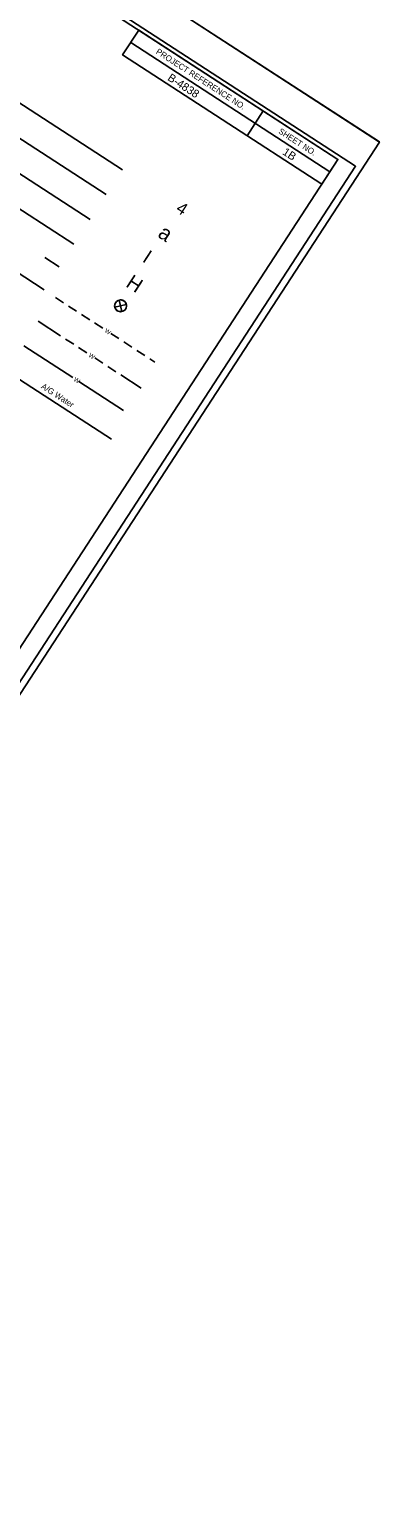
# Model space of a CAD drawing. Extents: x 2291197 to 2302790, y 592892 to 604246.
# Drawn here: x 2298300 to 2299243, y 592892 to 596884 of the extents above; entities that cross this region are included whole.
import ezdxf

# ---------------------------------------------------------------- set-up
doc = ezdxf.new("R2010")
doc.units = 0
for name, color, linetype in [('Default', 7, 'Continuous'), ('Prop Shade Light', 7, 'Continuous'), ('Sheet Cutting Line CELL', 7, 'Continuous'), ('Sheet Data Field CELL', 7, 'Continuous'), ('Sheet Plot Border Inside CELL', 7, 'Continuous'), ('Sheet Plot Border Outside CELL', 7, 'Continuous'), ('Sheet Symbology CELL', 7, 'Continuous')]:
    doc.layers.add(name, color=color, linetype=linetype)

# ---------------------------------------------------------------- blocks, each defined once
blk = doc.blocks.new('EXIST UTILITIES WATER TEST HOLE SUE LOS A')
at = {"layer": 'Default'}
for points in [[(0.043, 0.043), (-0.043, -0.043), (0, 0), (-0.043, 0.043), (0.043, -0.043)], [(-0.043, 0.043), (0, 0), (0.043, 0.043)], [(0.043, -0.043), (0, 0), (-0.043, -0.043)]]:
    blk.add_lwpolyline(points, dxfattribs=at)
blk.add_circle((0, 0), 0.0615, dxfattribs=at)
for start, end in [(45, 135), (225, 315)]:
    blk.add_arc((0, 0), 0.0615, start, end, dxfattribs=at)
blk = doc.blocks.new('PLAN SHEET SYMBOLOGY - New')
at = {"layer": 'Sheet Cutting Line CELL'}
blk.add_line((1439376.56, 921733.15), (1437692.56, 921733.15), dxfattribs=at)
at = {"layer": 'Sheet Plot Border Inside CELL'}
blk.add_lwpolyline([(1437705.56, 920655.6), (1439372.06, 920655.6), (1439372.06, 921710.7), (1437705.56, 921710.7)], close=True, dxfattribs=at)
at = {"layer": 'Sheet Plot Border Outside CELL'}
blk.add_lwpolyline([(1437692.56, 920633.15), (1439376.56, 920633.15), (1439376.56, 921733.15), (1437692.56, 921733.15)], close=True, dxfattribs=at)
at = {"layer": 'Sheet Symbology CELL'}
for p, q in [((1439299.56, 921708.11), (1439299.56, 921688.11)), ((1439199.52, 921698.11), (1439359.56, 921698.11)), ((1439199.52, 921688.11), (1439359.56, 921688.11)), ((1439241.62, 921623.14), (1439079.23, 921623.14)), ((1439241.62, 921603.14), (1439063.58, 921603.14)), ((1439241.62, 921583.14), (1439063.58, 921583.14)), ((1439241.62, 921563.14), (1439075.83, 921563.14)), ((1439241.62, 921545.05), (1439230.07, 921545.05)), ((1439241.62, 921526.41), (1439176.24, 921526.41)), ((1439250.79, 921526.19), (1439257.29, 921526.19)), ((1439261.29, 921526.19), (1439267.79, 921526.19)), ((1439271.79, 921526.19), (1439278.29, 921526.19)), ((1439282.29, 921526.19), (1439288.79, 921526.19)), ((1439295.19, 921526.19), (1439301.69, 921526.19)), ((1439305.69, 921526.19), (1439312.19, 921526.19)), ((1439316.19, 921526.19), (1439322.69, 921526.19)), ((1439326.69, 921526.19), (1439330.63, 921526.19)), ((1439249.66, 921506.41), (1439267.79, 921506.41)), ((1439271.79, 921506.41), (1439278.29, 921506.41)), ((1439282.29, 921506.41), (1439288.79, 921506.41)), ((1439295.19, 921506.41), (1439301.69, 921506.41)), ((1439305.69, 921506.41), (1439312.19, 921506.41)), ((1439316.19, 921506.41), (1439332.51, 921506.41)), ((1439250.63, 921487.28), (1439289.93, 921487.28)), ((1439294.93, 921487.28), (1439330.63, 921487.28)), ((1439250.63, 921466.62), (1439334.64, 921466.62))]:
    blk.add_line(p, q, dxfattribs=at)
for points in [[(1439359.56, 921708.15), (1437859.56, 921708.15), (1437859.56, 920659.17), (1439359.56, 920659.17)], [(1439199.52, 921708.15), (1439359.56, 921708.15), (1439359.56, 921688.11), (1439199.52, 921688.11)]]:
    blk.add_lwpolyline(points, close=True, dxfattribs=at)
at = {"layer": 'Default', "xscale": 65, "yscale": 65}
blk.add_blockref('EXIST UTILITIES WATER TEST HOLE SUE LOS A', (1439290.6, 921545.4), dxfattribs=at)
at = {"layer": 'Sheet Symbology CELL'}
for s, height, rotation, p in [('PROJECT REFERENCE NO.', 4, 360, (1439217.29, 921701.19)), ('SHEET NO.', 4, 360, (1439315.8, 921701.11)), ('a', 10.2, 0.00002, (1439285.53, 921598.04))]:
    blk.add_text(s, height=height, rotation=rotation, dxfattribs=at).set_placement(p)
for s, height, p in [('4', 8.25, (1439286.51, 921619.01)), ('I', 9.38, (1439285.94, 921578.45)), ('H', 9.75, (1439285.76, 921558.26)), ('W', 3, (1439290.89, 921524.69)), ('W', 3, (1439290.89, 921504.91)), ('W', 3, (1439291.33, 921485.78)), ('A/G Water', 4, (1439275.56, 921469.62))]:
    blk.add_text(s, height=height, dxfattribs=at).set_placement(p)

msp = doc.modelspace()

# ---------------------------------------------------------------- linework, layer by layer
at = {"layer": 'Sheet Cutting Line CELL'}
msp.add_line((2299242.9, 596580.9), (2293595.3, 600252.2), dxfattribs=at)

# ---------------------------------------------------------------- block references
at = {"layer": 'Prop Shade Light', "xscale": 4, "yscale": 3.9999999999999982, "rotation": -33.02629958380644}
msp.add_blockref('PLAN SHEET SYMBOLOGY - New', (-4537434.8, 643359.8), dxfattribs=at)

# ---------------------------------------------------------------- texts
at = {"layer": 'Sheet Data Field CELL'}
for s, p in [('B-4838', (2298670.2, 596749.2)), ('1B', (2298980, 596548.9))]:
    msp.add_text(s, height=21.6, rotation=326.9737, dxfattribs=at).set_placement(p)

doc.saveas('drawing.dxf')
